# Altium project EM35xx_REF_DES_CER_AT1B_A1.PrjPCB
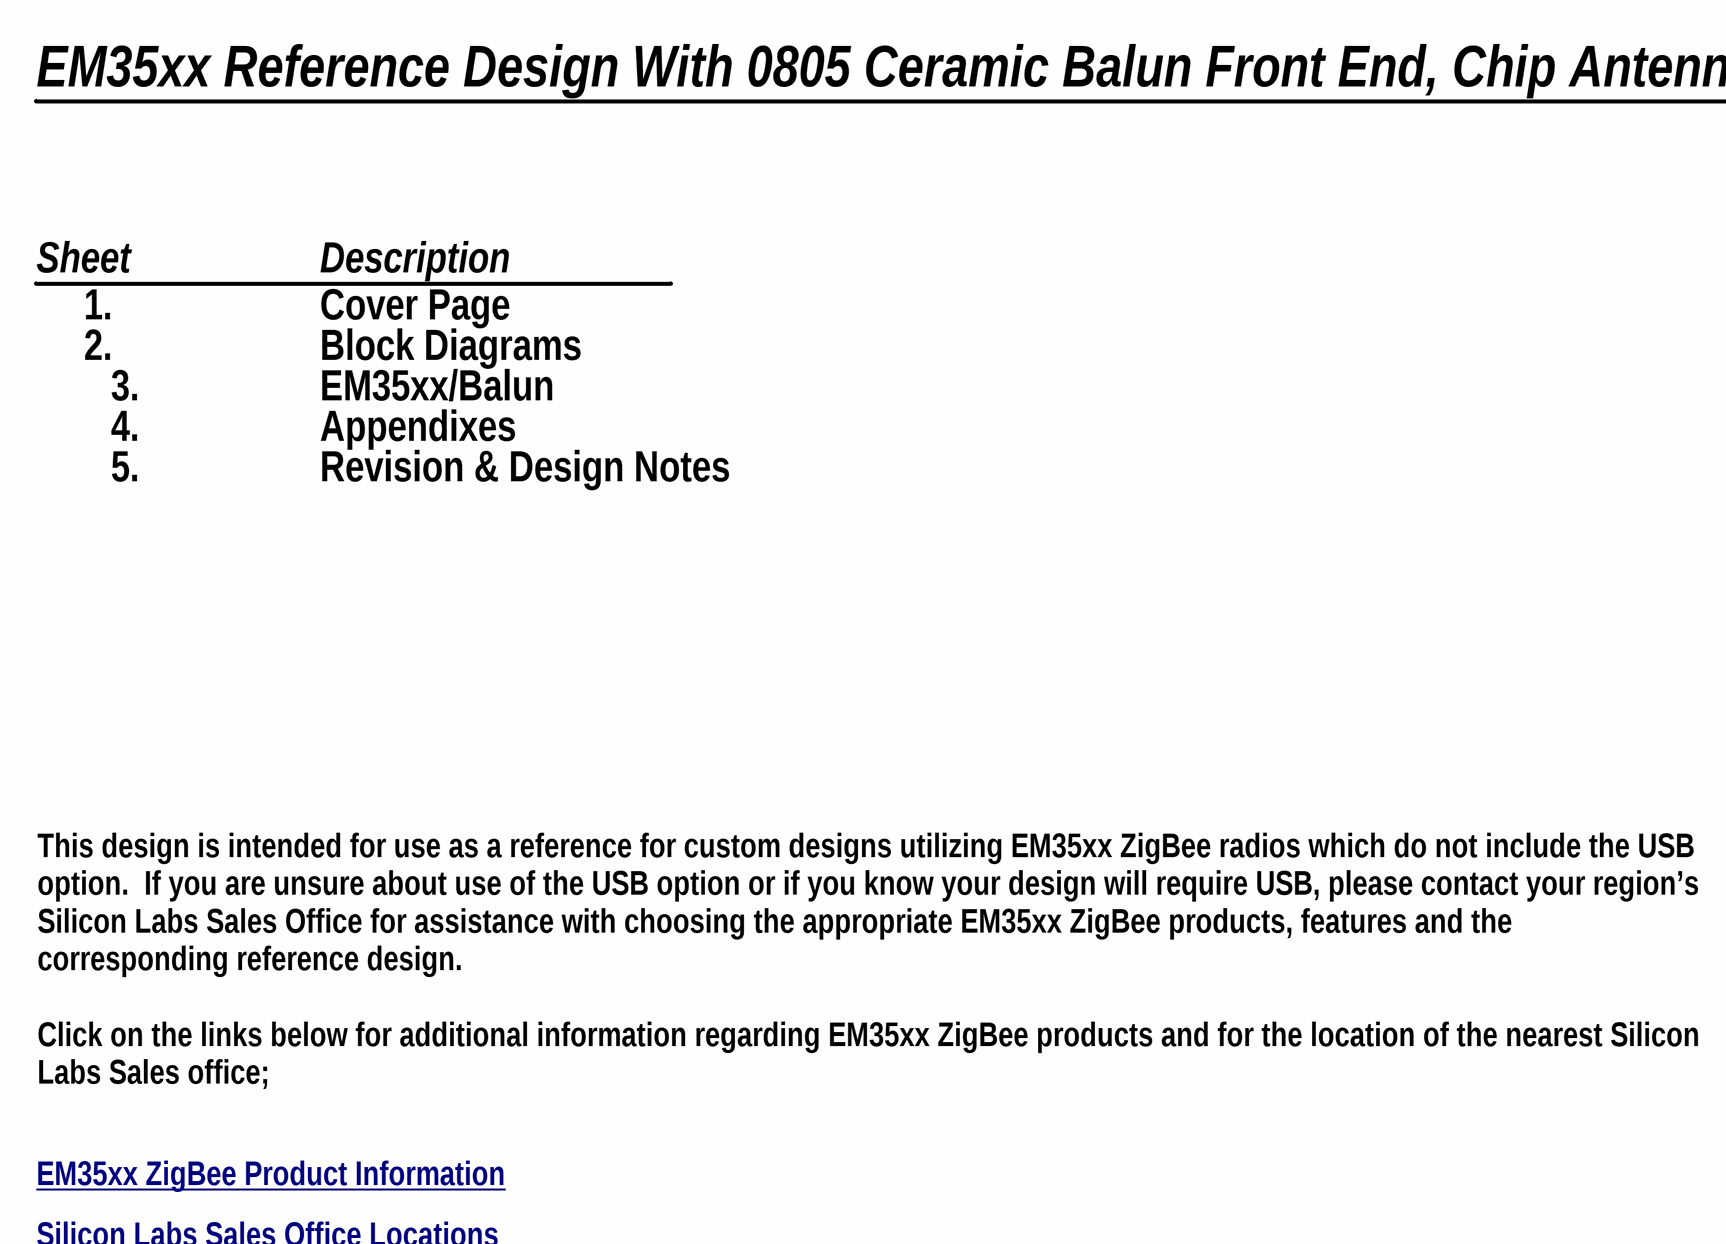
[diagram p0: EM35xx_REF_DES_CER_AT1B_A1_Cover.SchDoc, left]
Board Rev: A1; ClassName: PCB Only; Company Address 1: 25 Thomson Place; Company Address 2: 2nd Floor; Company Address 3: Boston, MA 02210; Company Design Group: MCU & Wireless Division Simplicity Support Group; Company Tel: 617-951-0200; Company Web Site: www.silabs.com; Title: EM35xx Ceramic Balun 2-Layer Reference Design
5 sheets, 52 parts. Net scope: global (net labels, ports and power ports of the same name join across sheets).
Board file: EM35xx_REF_DES_CER_AT1B_A1.PcbDoc
Sheets:
  EM35xx_REF_DES_CER_AT1B_A1_Cover.SchDoc
  EM35xx_REF_DES_CER_AT1B_A1_Block.SchDoc
  EM35xx_REF_DES_CER_AT1B_A1_Main.SchDoc
  EM35xx_REF_DES_CER_AT1B_A1_App.SchDoc
  EM35xx_REF_DES_CER_AT1B_A1_Notes.SchDoc

## Sheet EM35xx_REF_DES_CER_AT1B_A1_Cover.SchDoc: EM35xx/0805 Ceramic Balun Reference Design
size C; Organization: MCU & Wireless Division Simplicity Support Group; Address1: 25 Thomson Place, 2nd Floor; Address2: Boston, MA 02210, USA; Address3: www.silabs.com; Address4: 617-951-0200; Revision: A1; SheetNumber: 1; SheetTotal: 5

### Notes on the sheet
- EM35xx Reference Design With 0805 Ceramic Balun Front End, Chip Antenna, 2 - Layer
- Sheet
- Description
- 1.
- 2.
- Cover Page
- Block Diagrams
- 3.
- EM35xx/Balun
- 4.
- 5.
- Revision & Design Notes
- Appendixes
- This design is intended for use as a reference for custom designs utilizing EM35xx ZigBee radios which do not include the USB option.  If you are unsure about use of the USB option or if you know your design will require USB, please contact your region’s Silicon Labs Sales Office for assistance with choosing the appropriate EM35xx ZigBee products, features and the corresponding reference design.
  Click on the links below for additional information regarding EM35xx ZigBee products and for the location of the nearest Silicon Labs Sales office;
- EM35xx ZigBee Product Information <http://www.silabs.com/products/wireless/zigbee/Pages/default.aspx>
- Silicon Labs Sales Office Locations <http://www.silabs.com/buysample/pages/contact-sales.aspx>

## Sheet EM35xx_REF_DES_CER_AT1B_A1_Block.SchDoc: EM35xx/0805 Ceramic Balun Reference Design
size C; Organization: MCU & Wireless Division Simplicity Support Group; Address1: 25 Thomson Place, 2nd Floor; Address2: Boston, MA 02210, USA; Address3: www.silabs.com; Address4: 617-951-0200; Revision: A1; SheetNumber: 2; SheetTotal: 5
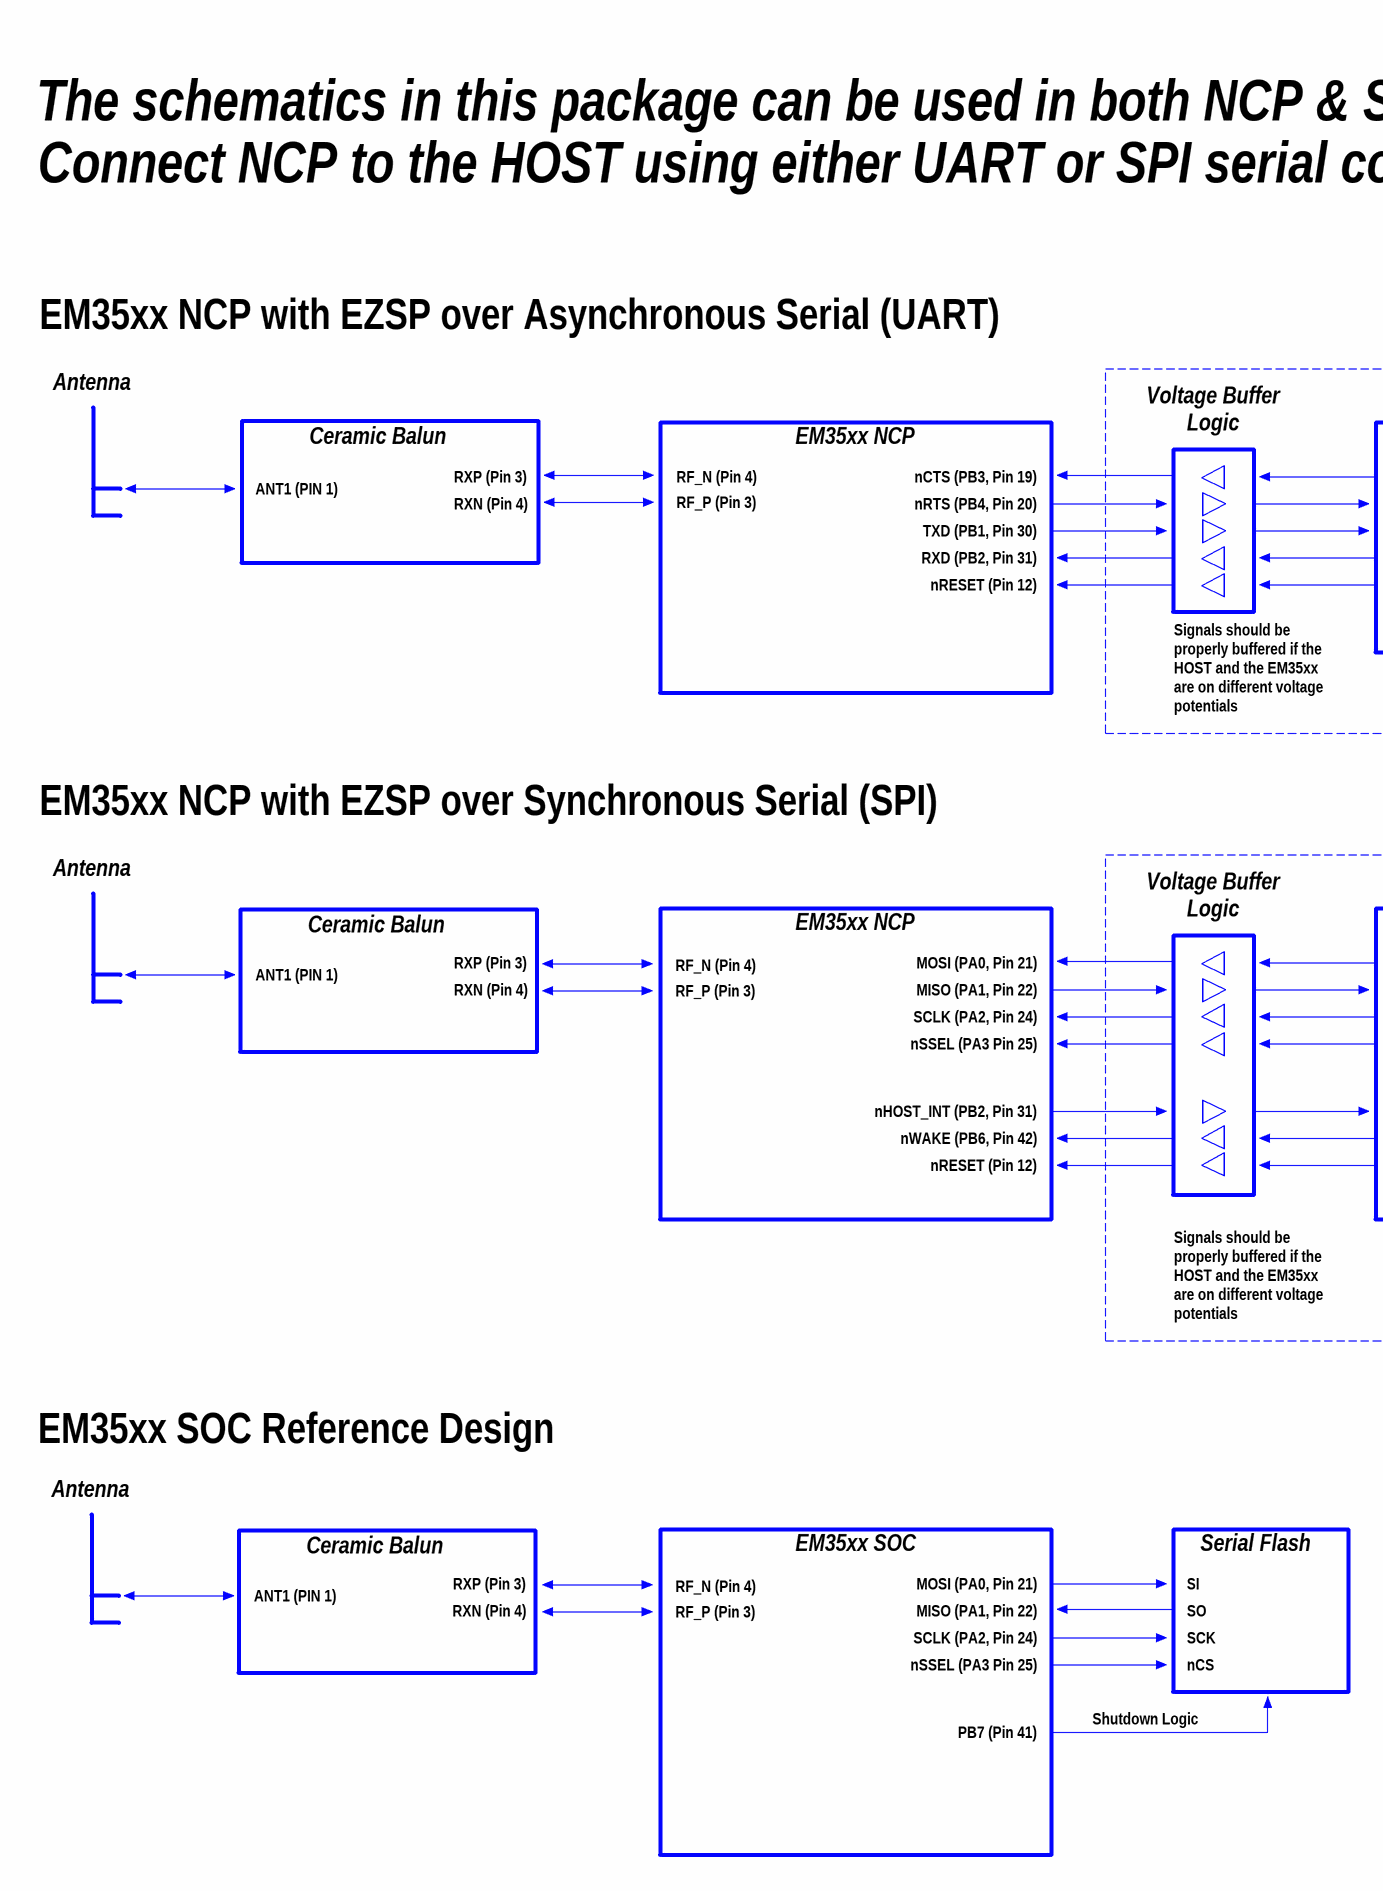
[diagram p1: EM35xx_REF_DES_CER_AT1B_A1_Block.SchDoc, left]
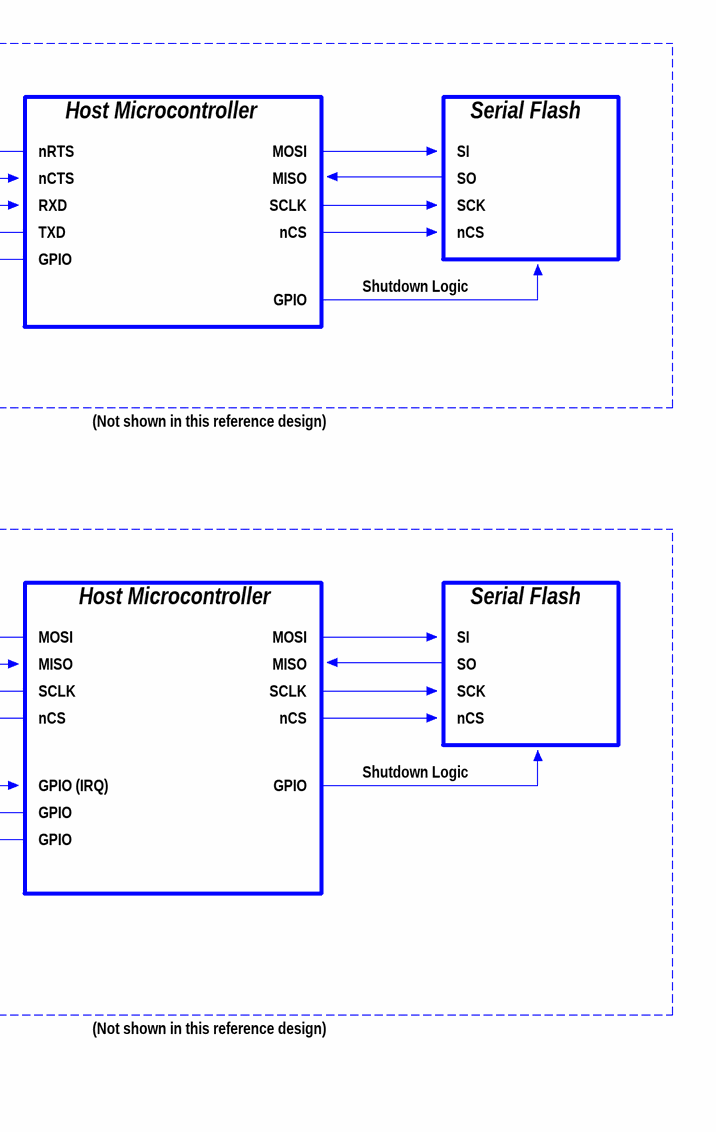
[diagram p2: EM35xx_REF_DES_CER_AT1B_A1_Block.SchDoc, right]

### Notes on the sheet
- The schematics in this package can be used in both NCP & SOC designs involving the EM35xx.
- Connect NCP to the HOST using either UART or SPI serial connection as shown below.
- EM35xx NCP with EZSP over Asynchronous Serial (UART)
- Antenna
- Voltage Buffer
- Ceramic Balun
- EM35xx NCP
- Logic
- Host Microcontroller
- Serial Flash
- ANT1 (PIN 1)
- RXP (Pin 3)
- RXN (Pin 4)
- RF_N (Pin 4)
- RF_P (Pin 3)
- nCTS (PB3, Pin 19)
- nRTS (PB4, Pin 20)
- TXD (PB1, Pin 30)
- nRTS
- nCTS
- RXD
- MOSI
- MISO
- SCLK
- SI
- SO
- SCK
- RXD (PB2, Pin 31)
- nRESET (Pin 12)
- TXD
- GPIO
- nCS
- Shutdown Logic
- Signals should be properly buffered if the HOST and the EM35xx are on different voltage potentials
- EM35xx NCP with EZSP over Synchronous Serial (SPI)
- (Not shown in this reference design)
- MOSI (PA0, Pin 21)
- MISO (PA1, Pin 22)
- SCLK (PA2, Pin 24)
- nSSEL (PA3 Pin 25)
- nHOST_INT (PB2, Pin 31)
- nWAKE (PB6, Pin 42)
- GPIO (IRQ)
- EM35xx SOC Reference Design
- EM35xx SOC
- PB7 (Pin 41)

## Sheet EM35xx_REF_DES_CER_AT1B_A1_Main.SchDoc: EM35xx/0805 Ceramic Balun Reference Design
size C; Organization: MCU & Wireless Division Simplicity Support Group; Address1: 25 Thomson Place, 2nd Floor; Address2: Boston, MA 02210, USA; Address3: www.silabs.com; Address4: 617-951-0200; Revision: A1; SheetNumber: 3; SheetTotal: 5
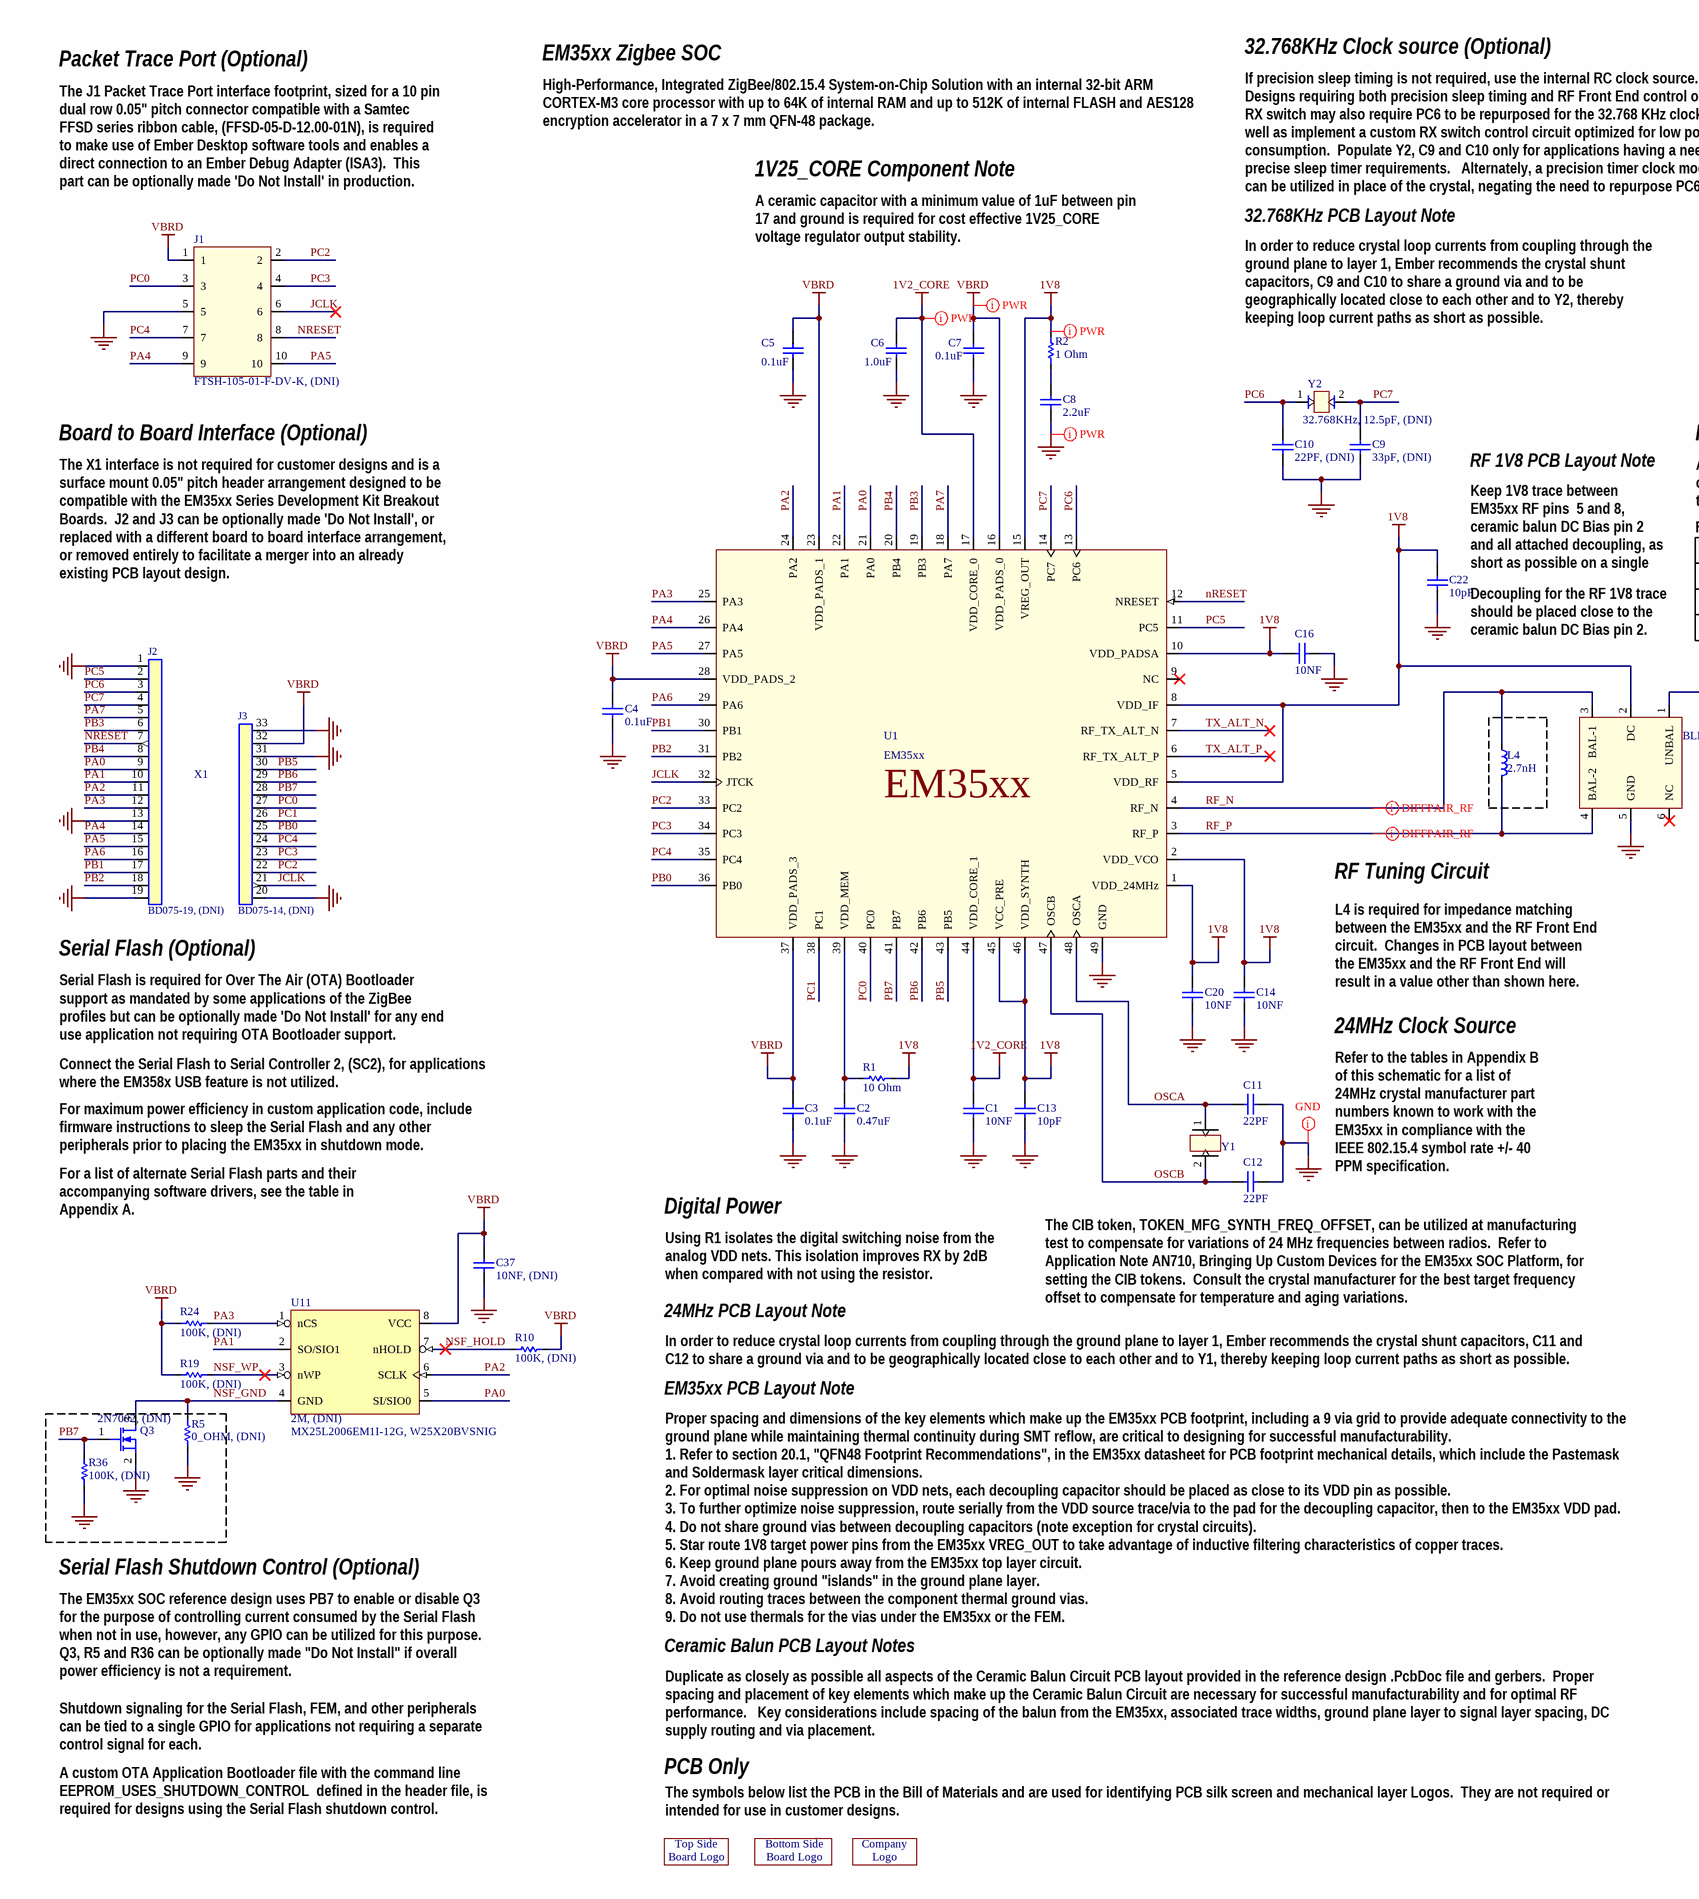
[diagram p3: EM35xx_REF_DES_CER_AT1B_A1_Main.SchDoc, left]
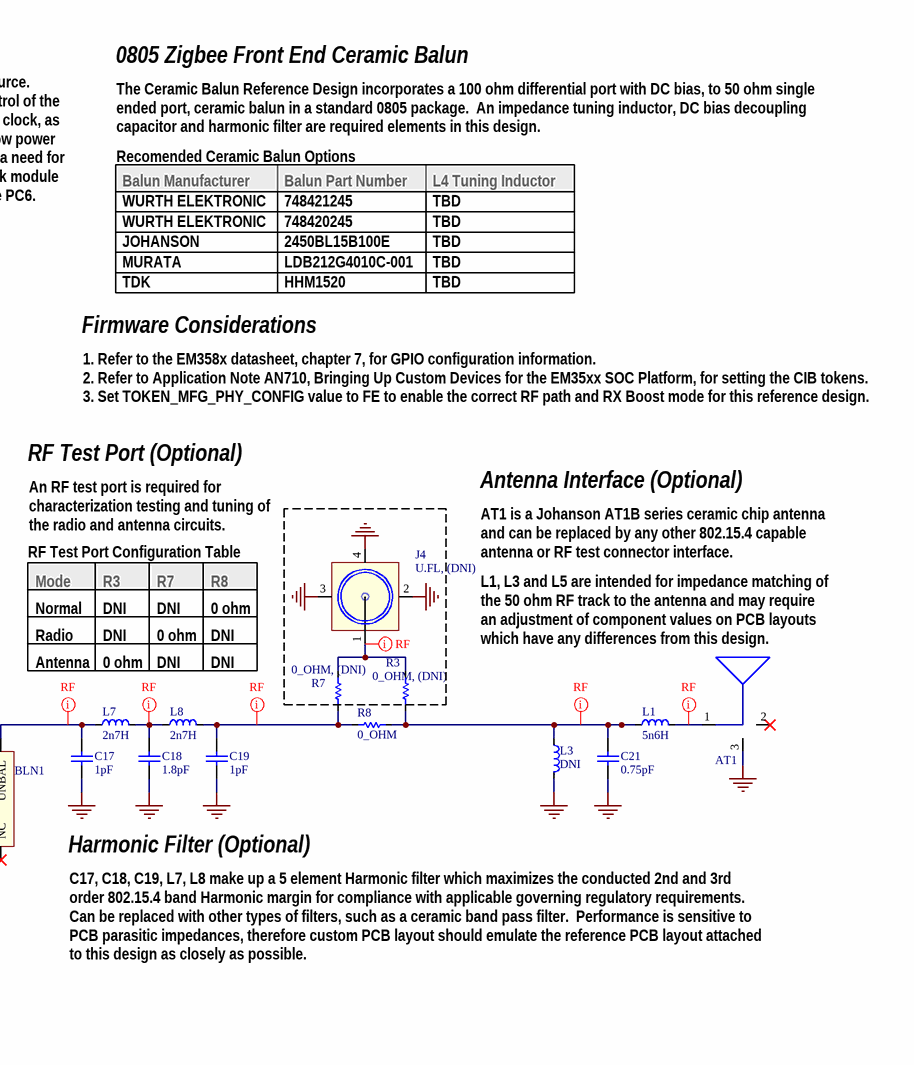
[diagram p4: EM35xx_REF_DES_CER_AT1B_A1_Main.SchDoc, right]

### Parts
AT1  (no value)  [Ant-Johanson-2450AT18B100]
BLN1  CHIP MULTILAYER CERAMIC, 2.4 GHZ. 50/100 Ohm  [BLN_0805]  (value not drawn)
C1  10NF  [C_0402]
C2  0.47uF  [C_0402]
C3  0.1uF  [C_0402]
C4  0.1uF  [C_0402]
C5  0.1uF  [C_0402]
C6  1.0uF  [C_0603]
C7  0.1uF  [C_0402]
C8  2.2uF  [C_0603]
C9  33pF, (DNI)  [C_0402]
C10  22PF, (DNI)  [C_0402]
C11  22PF  [C_0402]
C12  22PF  [C_0402]
C13  10pF  [C_0402]
C14  10NF  [C_0402]
C16  10NF  [C_0402]
C17  1pF  [C_0402]
C18  1.8pF  [C_0402]
C19  1pF  [C_0402]
C20  10NF  [C_0402]
C21  0.75pF  [C_0402]
C22  10pF  [C_0402]
C37  10NF, (DNI)  [C_0402]
J1  FTSH-105-01-F-DV-K, (DNI)  [610-0019-000-REF-DES]
J2  BD075-19, (DNI)  (mechanical)
J3  BD075-14, (DNI)  (mechanical)
J4  U.FL, (DNI)  [UFL-R-SMT_1]
L1  5n6H  [C_0402_Johanson_AT1B]
L3  DNI  [L_0402]
L4  2.7nH  [L_0603]
L7  2n7H  [L_0402]
L8  2n7H  [L_0402]
LOGO1  SiliconLabsLogo_100  [SiliconLabsLogo_100_Mech-16]  (value not drawn)  (no BOM)
PCB1  EM35x Ceramic Balun 2 Layer Reference Design Corporate Logo  [710-0651-009]  (value not drawn)
PCB2  Bottom Silk Screen ID and RoHS Text  [710-0651-009_ROHS]  (value not drawn)  (no BOM)
Q3  2N7002, (DNI)  [SOT23-3L]
R1  10 Ohm  [R_0402]
R2  1 Ohm  [R_0402]
R3  0_OHM, (DNI)  [R_0402]
R5  0_OHM, (DNI)  [R_0402]
R7  0_OHM, (DNI)  [R_0402]
R8  0_OHM  [R_0402]
R10  100K, (DNI)  [R_0402]
R19  100K, (DNI)  [R_0402]
R24  100K, (DNI)  [R_0402]
R36  100K, (DNI)  [R_0402]
U1  EM35xx  [EM357]
U11  2M, (DNI)  PART_NUMBER: MX25L2006EM1I-12G, W25X20BVSNIG  [SOIC127P600-8M]
X1  Dual Row Socket, (DNI)  [EM35X_RCM_MODULE_SIDE_SMT]  (value not drawn)  (no BOM)
Y1  24.000MHZ, 18PF LOAD  [HC-49-SMD]  (value not drawn)
Y2  32.768KHz, 12.5pF, (DNI)  [IL3X]

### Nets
1V2_CORE: C1.1 C6.1 U1.17(VDD_CORE_0) U1.44(VDD_CORE_1)
1V8: BLN1.2(DC) C13.1 C14.1 C16.1 C20.1 C22.1 R1.1 R2.1 U1.1(VDD_24MHz) U1.2(VDD_VCO) U1.5(VDD_RF) U1.8(VDD_IF) U1.10(VDD_PADSA) U1.15(VREG_OUT) U1.45(VCC_PRE) U1.46(VDD_SYNTH)
GND: AT1.3(GND) BLN1.5(GND) C1.2 C2.2 C3.2 C4.2 C5.2 C6.2 C7.2 C8.2 C9.2 C10.2 C11.2 C12.2 C13.2 C14.2 C16.2 C17.2 C18.2 C19.2 C20.2 C21.2 C22.2 C37.2 J1.5 J4.2(GND) J4.3(GND) J4.4(GND) L3.2 Q3.2(S) R5.2 R36.2 U1.49(GND) X1.1(GND) X1.13(GND) X1.19(GND) X1.20(GND) X1.31(GND) X1.33(GND)
VBRD: C3.1 C4.1 C5.1 C7.1 C37.1 J1.1 R10.2 R19.2 R24.2 U1.16(VDD_PADS_0) U1.23(VDD_PADS_1) U1.28(VDD_PADS_2) U1.37(VDD_PADS_3) U11.8(VCC) X1.32(VBRD)
JCLK: J1.6 U1.32(JTCK) X1.21(JCLK)
nRESET: J1.8 U1.12(NRESET) X1.7(nRESET)
NSF_GND: Q3.3(D) R5.1 U11.4(GND)
NSF_HOLD: R10.1 U11.7(nHOLD)
NSF_WP: R19.1 U11.3(nWP)
OSCA: C11.1 U1.48(OSCA) Y1.1(OSCB)
OSCB: C12.1 U1.47(OSCB) Y1.2(OSCA)
PA0: U1.21(PA0) U11.5(SI/SIO0) X1.9(PA0)
PA1: U1.22(PA1) U11.2(SO/SIO1) X1.10(PA1)
PA2: U1.24(PA2) U11.6(SCLK) X1.11(PA2)
PA3: R24.1 U1.25(PA3) U11.1(nCS) X1.12(PA3)
PA4: J1.9 U1.26(PA4) X1.14(PA4)
PA5: J1.10 U1.27(PA5) X1.15(PA5)
PA6: U1.29(PA6) X1.16(PA6)
PA7: U1.18(PA7) X1.5(PA7)
PB0: U1.36(PB0) X1.25(PB0)
PB1: U1.30(PB1) X1.17(PB1)
PB2: U1.31(PB2) X1.18(PB2)
PB3: U1.19(PB3) X1.6(PB3)
PB4: U1.20(PB4) X1.8(PB4)
PB5: U1.43(PB5) X1.30(PB5)
PB6: U1.42(PB6) X1.29(PB6)
PB7: Q3.1(G) R36.1 U1.41(PB7) X1.28(PB7)
PC0: J1.3 U1.40(PC0) X1.27(PC0)
PC1: U1.38(PC1) X1.26(PC1)
PC2: J1.2 U1.33(PC2) X1.22(PC2)
PC3: J1.4 U1.34(PC3) X1.23(PC3)
PC4: J1.7 U1.35(PC4) X1.24(PC4)
PC5: U1.11(PC5) X1.2(PC5)
PC6: C10.1 U1.13(PC6) X1.3(PC6) Y2.1
PC7: C9.1 U1.14(PC7) X1.4(PC7) Y2.2
RF_N: BLN1.3(BAL-1) L4.1 U1.4(RF_N)
RF_P: BLN1.4(BAL-2) L4.2 U1.3(RF_P)
TX_ALT_N: U1.7(RF_TX_ALT_N)
TX_ALT_P: U1.6(RF_TX_ALT_P)
NetAT1_1: AT1.1 L1.2
NetAT1_4: AT1.4 C21.1 L1.1 L3.1 R3.1 R8.2
NetBLN1_1: BLN1.1(UNBAL) C17.1 L7.1
NetC2_1: C2.1 R1.2 U1.39(VDD_MEM)
NetC8_1: C8.1 R2.2
NetC18_1: C18.1 L7.2 L8.1
NetC19_1: C19.1 L8.2 R7.1 R8.1
NetJ4_1: J4.1(SIGNAL) R3.2 R7.2

Not connected (* = marked no-connect by the designer): AT1 2*; BLN1 6(NC)*; U1 9(NC)*

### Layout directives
rule Width Constraint [Pref Width = 20mil    Min Width = 5mil    Max Width = 40mil]: 1V2_CORE, 1V8, VBRD
rule Width Constraint [Pref Width = 28mil    Min Width = 6mil    Max Width = 60mil]; rule Clearance Constraint [Clearance = 6mil]: NetAT1_1, NetAT1_4, NetBLN1_1, NetC18_1, NetC19_1, NetJ4_1
differential pair; rule Width Constraint [Pref Width = 7mil    Min Width = 5mil    Max Width = 10mil]; rule Matched Net Lengths [Tolerance = 2.5mil]: RF_N, RF_P
rule Clearance Constraint [Clearance = 9.5mil]: GND
rule Width Constraint [Pref Width = 20mil    Min Width = 5mil    Max Width = 40mil]; rule Short-Circuit Constraint [Short Circuit - Allowed]: GND

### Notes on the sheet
- Packet Trace Port (Optional)
- EM35xx Zigbee SOC
- 32.768KHz Clock source (Optional)
- 0805 Zigbee Front End Ceramic Balun
- High-Performance, Integrated ZigBee/802.15.4 System-on-Chip Solution with an internal 32-bit ARM CORTEX-M3 core processor with up to 64K of internal RAM and up to 512K of internal FLASH and AES128 encryption accelerator in a 7 x 7 mm QFN-48 package.
- The Ceramic Balun Reference Design incorporates a 100 ohm differential port with DC bias, to 50 ohm single ended port, ceramic balun in a standard 0805 package.  An impedance tuning inductor, DC bias decoupling capacitor and harmonic filter are required elements in this design.
- Recomended Ceramic Balun Options
- The J1 Packet Trace Port interface footprint, sized for a 10 pin dual row 0.05" pitch connector compatible with a Samtec FFSD series ribbon cable, (FFSD-05-D-12.00-01N), is required to make use of Ember Desktop software tools and enables a direct connection to an Ember Debug Adapter (ISA3).  This part can be optionally made 'Do Not Install' in production.
- 1V25_CORE Component Note
- If precision sleep timing is not required, use the internal RC clock source.  Designs requiring both precision sleep timing and RF Front End control of the RX switch may also require PC6 to be repurposed for the 32.768 KHz clock, as well as implement a custom RX switch control circuit optimized for low power consumption.  Populate Y2, C9 and C10 only for applications having a need for precise sleep timer requirements.   Alternately, a precision timer clock module can be utilized in place of the crystal, negating the need to repurpose PC6.
- WURTH ELEKTRONIC
- Balun Manufacturer
- 748421245
- Balun Part Number
- L4 Tuning Inductor
- TBD
- A ceramic capacitor with a minimum value of 1uF between pin 17 and ground is required for cost effective 1V25_CORE voltage regulator output stability.
- 32.768KHz PCB Layout Note
- JOHANSON
- MURATA
- TDK
- 2450BL15B100E
- 748420245
- LDB212G4010C-001
- HHM1520
- In order to reduce crystal loop currents from coupling through the ground plane to layer 1, Ember recommends the crystal shunt capacitors, C9 and C10 to share a ground via and to be geographically located close to each other and to Y2, thereby keeping loop current paths as short as possible.
- Firmware Considerations
- 1. Refer to the EM358x datasheet, chapter 7, for GPIO configuration information.
  2. Refer to Application Note AN710, Bringing Up Custom Devices for the EM35xx SOC Platform, for setting the CIB tokens.
  3. Set TOKEN_MFG_PHY_CONFIG value to FE to enable the correct RF path and RX Boost mode for this reference design.
- Board to Board Interface (Optional)
- RF 1V8 PCB Layout Note
- RF Test Port (Optional)
- Antenna Interface (Optional)
- An RF test port is required for characterization testing and tuning of the radio and antenna circuits.
- (near J4) RF Test Port Configuration Table
- AT1 is a Johanson AT1B series ceramic chip antenna and can be replaced by any other 802.15.4 capable antenna or RF test connector interface.
- The X1 interface is not required for customer designs and is a surface mount 0.05" pitch header arrangement designed to be compatible with the EM35xx Series Development Kit Breakout Boards.  J2 and J3 can be optionally made 'Do Not Install', or replaced with a different board to board interface arrangement, or removed entirely to facilitate a merger into an already existing PCB layout design.
- (near C22) Keep 1V8 trace between EM35xx RF pins  5 and 8, ceramic balun DC Bias pin 2 and all attached decoupling, as short as possible on a single layer.
- Mode
- Normal
- R3
- DNI
- R7
- R8
- 0 ohm
- (near C22) Decoupling for the RF 1V8 trace should be placed close to the ceramic balun DC Bias pin 2.
- Antenna
- Radio
- L1, L3 and L5 are intended for impedance matching of the 50 ohm RF track to the antenna and may require an adjustment of component values on PCB layouts which have any differences from this design.
- Harmonic Filter (Optional)
- RF Tuning Circuit
- C17, C18, C19, L7, L8 make up a 5 element Harmonic filter which maximizes the conducted 2nd and 3rd order 802.15.4 band Harmonic margin for compliance with applicable governing regulatory requirements.   Can be replaced with other types of filters, such as a ceramic band pass filter.  Performance is sensitive to PCB parasitic impedances, therefore custom PCB layout should emulate the reference PCB layout attached to this design as closely as possible.
- (near X1) Serial Flash (Optional)
- L4 is required for impedance matching between the EM35xx and the RF Front End circuit.  Changes in PCB layout between the EM35xx and the RF Front End will result in a value other than shown here.
- (near J2) Serial Flash is required for Over The Air (OTA) Bootloader support as mandated by some applications of the ZigBee profiles but can be optionally made 'Do Not Install' for any end use application not requiring OTA Bootloader support.
- 24MHz Clock Source
- (near J2) Connect the Serial Flash to Serial Controller 2, (SC2), for applications where the EM358x USB feature is not utilized.
- For maximum power efficiency in custom application code, include firmware instructions to sleep the Serial Flash and any other peripherals prior to placing the EM35xx in shutdown mode.
- Refer to the tables in Appendix B of this schematic for a list of 24MHz crystal manufacturer part numbers known to work with the EM35xx in compliance with the IEEE 802.15.4 symbol rate +/- 40 PPM specification.
- For a list of alternate Serial Flash parts and their accompanying software drivers, see the table in Appendix A.
- Digital Power
- Using R1 isolates the digital switching noise from the analog VDD nets. This isolation improves RX by 2dB when compared with not using the resistor.
- (near C12) The CIB token, TOKEN_MFG_SYNTH_FREQ_OFFSET, can be utilized at manufacturing test to compensate for variations of 24 MHz frequencies between radios.  Refer to Application Note AN710, Bringing Up Custom Devices for the EM35xx SOC Platform, for setting the CIB tokens.  Consult the crystal manufacturer for the best target frequency offset to compensate for temperature and aging variations.
- In order to reduce crystal loop currents from coupling through the ground plane to layer 1, Ember recommends the crystal shunt capacitors, C11 and C12 to share a ground via and to be geographically located close to each other and to Y1, thereby keeping loop current paths as short as possible.
- 24MHz PCB Layout Note
- EM35xx PCB Layout Note
- Serial Flash Shutdown Control (Optional)
- Proper spacing and dimensions of the key elements which make up the EM35xx PCB footprint, including a 9 via grid to provide adequate connectivity to the ground plane while maintaining thermal continuity during SMT reflow, are critical to designing for successful manufacturability.
  1. Refer to section 20.1, "QFN48 Footprint Recommendations", in the EM35xx datasheet for PCB footprint mechanical details, which include the Pastemask and Soldermask layer critical dimensions.
  2. For optimal noise suppression on VDD nets, each decoupling capacitor should be placed as close to its VDD pin as possible.
  3. To further optimize noise suppression, route serially from the VDD source trace/via to the pad for the decoupling capacitor, then to the EM35xx VDD pad.
  4. Do not share ground vias between decoupling capacitors (note exception for crystal circuits).
  5. Star route 1V8 target power pins from the EM35xx VREG_OUT to take advantage of inductive filtering characteristics of copper traces.
  6. Keep ground plane pours away from the EM35xx top layer circuit.
  7. Avoid creating ground "islands" in the ground plane layer.
  8. Avoid routing traces between the component thermal ground vias.
  9. Do not use thermals for the vias under the EM35xx or the FEM.
- The EM35xx SOC reference design uses PB7 to enable or disable Q3 for the purpose of controlling current consumed by the Serial Flash when not in use, however, any GPIO can be utilized for this purpose.  Q3, R5 and R36 can be optionally made "Do Not Install" if overall power efficiency is not a requirement.
- Ceramic Balun PCB Layout Notes
- Shutdown signaling for the Serial Flash, FEM, and other peripherals can be tied to a single GPIO for applications not requiring a separate control signal for each.
- Duplicate as closely as possible all aspects of the Ceramic Balun Circuit PCB layout provided in the reference design .PcbDoc file and gerbers.  Proper spacing and placement of key elements which make up the Ceramic Balun Circuit are necessary for successful manufacturability and for optimal RF performance.   Key considerations include spacing of the balun from the EM35xx, associated trace widths, ground plane layer to signal layer spacing, DC supply routing and via placement.
- PCB Only
- The symbols below list the PCB in the Bill of Materials and are used for identifying PCB silk screen and mechanical layer Logos.  They are not required or intended for use in customer designs.
- A custom OTA Application Bootloader file with the command line  EEPROM_USES_SHUTDOWN_CONTROL  defined in the header file, is required for designs using the Serial Flash shutdown control.

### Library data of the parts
AT1 = 600-0044-000: Part Description: ANTENNA, CERAMIC CHIP DIELECTRIC, 3.2X1.6X0.5MM, 2.45GHZ
BLN1 = 566-0075-000: Balun 0805; Part Description: BALUN, CHIP MULTILAYER CERAMIC, 2.4 GHZ. 50/100 OHM, -40C TO 85C, 0805 (2012 METRIC); Temperature Coefficient: -40C to 85C
C1 C14 C20 = 550-0036-000: Part Description: CAPACITOR, CERAMIC, 10NF, +/-10%, 6.3V, -55C TO 125C, X7R, 0402 (1005 METRIC); MANUFACTURER: MURATA; PART_NUMBER: GRM155R70J103KA01D; VOLTAGE: 6.3V; TOLERANCE: +/-10%; Temperature Coefficient: -55C to 125C, X7R
C2 = 550-0037-000: Part Description: CAPACITOR, CERAMIC, 0.47UF, +/- 10%, 6.3V, -55C TO 85C, X5R, 0402 (1005 METRIC); MANUFACTURER: MURATA; PART_NUMBER: GRM155R60J474KE19D; VOLTAGE: 6.3V; TOLERANCE: +/- 10%; Temperature Coefficient: -55C to 85C, X5R
C3-C5 C7 = 550-0034-000: Part Description: CAPACITOR, CERAMIC, 0.1UF, +/-10%, 6.3V, -55C TO 125C, X7R, 0402 (1005 METRIC); MANUFACTURER: MURATA; PART_NUMBER: GRM155R70J104KA01D; VOLTAGE: 6.3V; TOLERANCE: +/-10%; Temperature Coefficient: -55C to 125C, X7R
C6 = 550-0033-000: Part Description: CAPACITOR, CERAMIC, 1.0UF, +/-10%, 10V, -55C TO 125C, X7R, 0603 (1608 METRIC); MANUFACTURER: TAIYO YUDEN LTD; PART_NUMBER: LMK107B7105KA-T; VOLTAGE: 10V; TOLERANCE: +/-10%; Temperature Coefficient: -55C to 125C, X7R
C8 = 550-0038-000: Part Description: CAPACITOR, CERAMIC, 2.2UF, +/-10%, 6.3V, -55C TO 125C, X7R, 0603 (1608 METRIC); MANUFACTURER: MURATA; PART_NUMBER: CL10B225KQ8NNNC; VOLTAGE: 6.3V; TOLERANCE: +/-10%; Temperature Coefficient: -55C to 125C, X7R
C9 = 550-0039-000-DNI: Part Description: CAPACITOR, CERAMIC, 33PF, (DNI), +/-5%, 50V, -55C TO 125C, C0G, NP0, 0402 (1005 METRIC); MANUFACTURER: SAMSUNG ELECTRONICS; PART_NUMBER: CL05C330JB5NNNC; VOLTAGE: 50V; TOLERANCE: +/-5%; Temperature Coefficient: -55C to 125C, C0G, NP0
C10 = 550-2201-050-DNI: Part Description: CAPACITOR, CERAMIC, 22PF, +/-5%, 50V, -55C TO 125C, 0402 (1005 METRIC); MANUFACTURER: MURATA; PART_NUMBER: GRM1555C1H220JZ01D; VOLTAGE: 50V; TOLERANCE: +/-5%; Temperature Coefficient: -55C to 125C
C11 C12 = 550-2201-050: Part Description: CAPACITOR, CERAMIC, 22PF, +/-5%, 50V, -55C TO 125C, 0402 (1005 METRIC); MANUFACTURER: MURATA; PART_NUMBER: GRM1555C1H220JZ01D; VOLTAGE: 50V; TOLERANCE: +/-5%; Temperature Coefficient: -55C to 125C
C13 C22 = 550-1001-050: Part Description: CAPACITOR, CERAMIC, 10PF, +/-5%, 50V, -55C TO 125C, 0402 (1005 METRIC); MANUFACTURER: MURATA; PART_NUMBER: GRM1555C1H100JZ01D; VOLTAGE: 50V; TOLERANCE: +/-5%; Temperature Coefficient: -55C to 125C
C16 = 550-0036-000: Part Description: CAPACITOR, CERAMIC, 10NF, +/-10%, 6.3V, -55C TO 125C, X7R, 0402 (1005 METRIC); MANUFACTURER: MURATA; PART_NUMBER: GRM155R70J103KA01D; TOLERANCE: +/-10%; Temperature Coefficient: -55C to 125C, X7R; VOLTAGE: 6.3V
C17 C19 = 550-0040-000: Part Description: CAPACITOR, CERAMIC, 1PF, +/-0.25PF, 50V, -55C TO 125C, C0G, NP0, 0402 (1005 METRIC); MANUFACTURER: SAMSUNG ELECTRONICS; PART_NUMBER: CL05C010CB5NNNC; VOLTAGE: 50V; TOLERANCE: +/-0.25pF; Temperature Coefficient: -55C to 125C, C0G, NP0
C18 = 550-1P8A-050: Part Description: CAPACITOR, CERAMIC, 1.8PF, +/-0.25PF, 50V, -55C TO 125C, C0G, NP0, 0402 (1005 METRIC); MANUFACTURER: MURATA; PART_NUMBER: GRM1555C1H1R8CZ01D; VOLTAGE: 50V; TOLERANCE: +/-0.25pF; Temperature Coefficient: -55C to 125C, C0G, NP0
C21 = 550-0045-000: Part Description: CAPACITOR, CERAMIC, 0.75PF, +/-0.25PF, 50V, -55C TO 125C, C0G, NP0, 0402 (1005 METRIC); MANUFACTURER: MURATA; PART_NUMBER: GRM1555C1HR75CA01D; VOLTAGE: 50V; TOLERANCE: +/-0.25pF; Temperature Coefficient: -55C to 125C, C0G, NP0
C37 = 550-0036-000-DNI: Part Description: CAPACITOR, CERAMIC, 10NF, (DNI), +/-10%, 6.3V, -55C TO 125C, X7R, 0402 (1005 METRIC); MANUFACTURER: MURATA; PART_NUMBER: GRM155R70J103KA01D; VOLTAGE: 6.3V; TOLERANCE: +/-10%; Temperature Coefficient: -55C to 125C, X7R
J1 = 610-0045-000-DNI: CONNECTOR, HEADER, SHROUDED, 10 POSITION, DUAL ROW, VERTICAL, 0.050"; Part Description: CONNECTOR, HEADER, FTSH-105-01-F-DV-K, (DNI), 10 POSITION, DUAL ROW, VERTICAL, 0.050"
J2 = 610-0086-000-DNI: 19 pin, 0.050" pitch  RCM socket, SMT; Part Description: CONNECTOR, RECEPTACLE, BD075-19, (DNI), SURFACE MOUNT VERTICAL; MANUFACTURER: Global Connector Technology; PART_NUMBER: BD075-19-A-1-L-C
J3 = 610-0087-000-DNI: 14 pin, 0.050" pitch  RCM socket, SMT; Part Description: CONNECTOR, RECEPTACLE, BD075-14, (DNI), SURFACE MOUNT VERTICAL; MANUFACTURER: Global Connector Technology; PART_NUMBER: BD075-14-A-1-L-C
J4 = 610-0081-000-DNI: U.FL RF Coaxial Connector; Part Description: CONNECTOR, RECEPTACLE, U.FL, (DNI), RF COAXIAL, SMT; MANUFACTURER: Molex; PART_NUMBER: 73412-0110
L1 = 566-0077-000: Design Placeholder; Part Description: INDUCTOR, MULTI-LAYER FILM, 5N6H, +/-0.3NH, 300MA, -55C TO 125C, 0402 (1005 METRIC); MANUFACTURER: MURATA; PART_NUMBER: LQG15HS5N6S02D; Current Rating: 300MA; TOLERANCE: +/-0.3NH; Temperature Coefficient: -55C to 125C
L3 = 566-0000-TBD: Design Placeholder; Part Description: INDUCTOR, TBD
L4 = 566-0076-000: Design Placeholder; Part Description: INDUCTOR, MULTI-LAYER FILM, 2.7NH, +/-0.3NH, -40C TO 85C, 0603 (1608 METRIC); MANUFACTURER: MURATA; PART_NUMBER: LQG18HN2N7S00D; TOLERANCE: +/-0.3NH; Temperature Coefficient: -40C to 85C
L7 L8 = 566-2N7A-000: Design Placeholder; Part Description: INDUCTOR, MULTI-LAYER FILM, 2N7H, +/-0.3NH, 300MA, -55C TO 125C, 0402 (1005 METRIC); MANUFACTURER: MURATA; PART_NUMBER: LQG15HS2N7S02D; Current Rating: 300MA; TOLERANCE: +/-0.3NH; Temperature Coefficient: -55C to 125C
LOGO1 = SiliconLabsLogo_100: Company Logo in PCB Title Block
PCB1 = 710-0651-009: PCB BoM ID and Top Side Silk Screen Identifier; Part Description: MECHANICAL, PCB, EM35X CERAMIC BALUN 2 LAYER REFERENCE DESIGN CORPORATE LOGO
PCB2 = 710-0651-009_ROHS: Bottom Side Silk Screen Identifier; Part Description: MECHANICAL, PCB, EM35X CERAMIC BALUN 2 LAYER REFERENCE DESIGN BOTTOM SIDE CORPORATE LOGO W/ROHS LOGO; VALUE: EM35x Ceramic Balun 2 Layer Reference Design Bottom Side Corporate Logo w/ROHS logo
Q3 = 545-0047-000-DNI: MOSFET N-Channel; Part Description: MOSFET, 2N7002, (DNI), 300MA, 830MW, 60V, TO-236-3, SC-59, SOT-23-3; VOLTAGE: 60V; POWER: 830mW; Current Rating: 300mA
R1 = 555-1001-010: Part Description: RESISTOR, THICK FILM, 10 OHM, +/-1%, 0.1W, 1/10W, 0402 (1005 METRIC); POWER: 0.1W, 1/10W; TOLERANCE: +/-1%; Temperature Coefficient: +/-100ppm/C
R2 = 555-1R05-016: Part Description: RESISTOR, THICK FILM, 1 OHM, +/-5%, 0.1W, 1/10W, 0402 (1005 METRIC); POWER: 0.1W, 1/10W; TOLERANCE: +/-5%; Temperature Coefficient: -100/ +600ppm/C
R3 R5 R7 = 555-0000-000-DNI: Part Description: RESISTOR, THICK FILM, 0_OHM, (DNI), JUMPER, 1/10W, 0402 (1005 METRIC); MANUFACTURER: SAMSUNG ELECTRONICS; PART_NUMBER: RC1005J000CS; POWER: 1/10W; TOLERANCE: Jumper; Temperature Coefficient: -100/ +600ppm/C
R8 = 555-0000-000: Part Description: RESISTOR, THICK FILM, 0_OHM, JUMPER, 1/10W, 0402 (1005 METRIC); POWER: 1/10W; TOLERANCE: Jumper; Temperature Coefficient: -100/ +600ppm/C
R10 R19 R36 = 555-1045-016-DNI: Part Description: RESISTOR, THICK FILM, 100K, (DNI), +/-5%, 0.1W, 1/10W, 0402 (1005 METRIC); POWER: 0.1W, 1/10W; TOLERANCE: +/-5%; Temperature Coefficient: +/-200ppm/C
R24 = 555-1045-016-DNI: Part Description: RESISTOR, THICK FILM, 100K, (DNI), +/-5%, 0.1W, 1/10W, 0402 (1005 METRIC); TOLERANCE: +/-5%; POWER: 0.1W, 1/10W; Temperature Coefficient: +/-200ppm/C
U1 = 540-035XX-000: IC, EM357, ZIGBEE/802.15.4 RF SOLUTION, ARM CORTEX-M3, 12K RAM, 192K FLASH, QFN-48; Part Description: IC, COMMUNICATIONS, EM35XX, -40C TO 85C, SOC, ZIGBEE/802.15.4 RF TRANSCEIVER, ARM CORTEX-M3, TO 12 - 64K RAM, 128 - 512K FLASH, 48-QFN; MANUFACTURER: SILICON LABS; PART_NUMBER: 540-035x-000
U11 = 510-1040-000-DNI: IC - MEMORY, SERIAL FLASH, 2M (2M X 1, 1M X 2), 2.7 V - 3.6 V, -40C  85C, 8-SOIC (0.154", 3.90MM WIDTH); Part Description: IC - PROGRAMMABLE MEMORY - BLANK, SERIAL FLASH, 2M, (DNI), 2.7 V - 3.6 V, -40C  85C, 8-SOIC (0.154IN, 3.90MM WIDTH); MANUFACTURER: MACRONIX, WINBOND
X1 = 610-0010-DNI: Part Description: CONNECTOR, INTERFACE, RCM, DEV KIT, EM35X, DUAL ROW SOCKET, (DNI)
Y1 = 565-2400-009: OSCILLATOR, CRYSTAL, 24.000MHZ, 18PF LOAD, +/-10PPM TOLERANCE, +/-25PPM STABILITY, -40C TO 85C, AT49; MANUFACTURER: ABRACON
Y2 = 565-3271-001-DNI: Part Description: OSCILLATOR, CRYSTAL, 32.768KHZ, 12.5PF, (DNI), +/-20PPM, -40C TO 85C, 2-SMD; MANUFACTURER: ABRACON; PART_NUMBER: ABS07-32.768KHZ-T; TOLERANCE: +/-20ppm; Temperature Coefficient: -40C to 85C

## Sheet EM35xx_REF_DES_CER_AT1B_A1_App.SchDoc: EM35xx/0805 Ceramic Balun Reference Design
size C; Organization: MCU & Wireless Division Simplicity Support Group; Address1: 25 Thomson Place, 2nd Floor; Address2: Boston, MA 02210, USA; Address3: www.silabs.com; Address4: 617-951-0200; Revision: A1; SheetNumber: 4; SheetTotal: 5
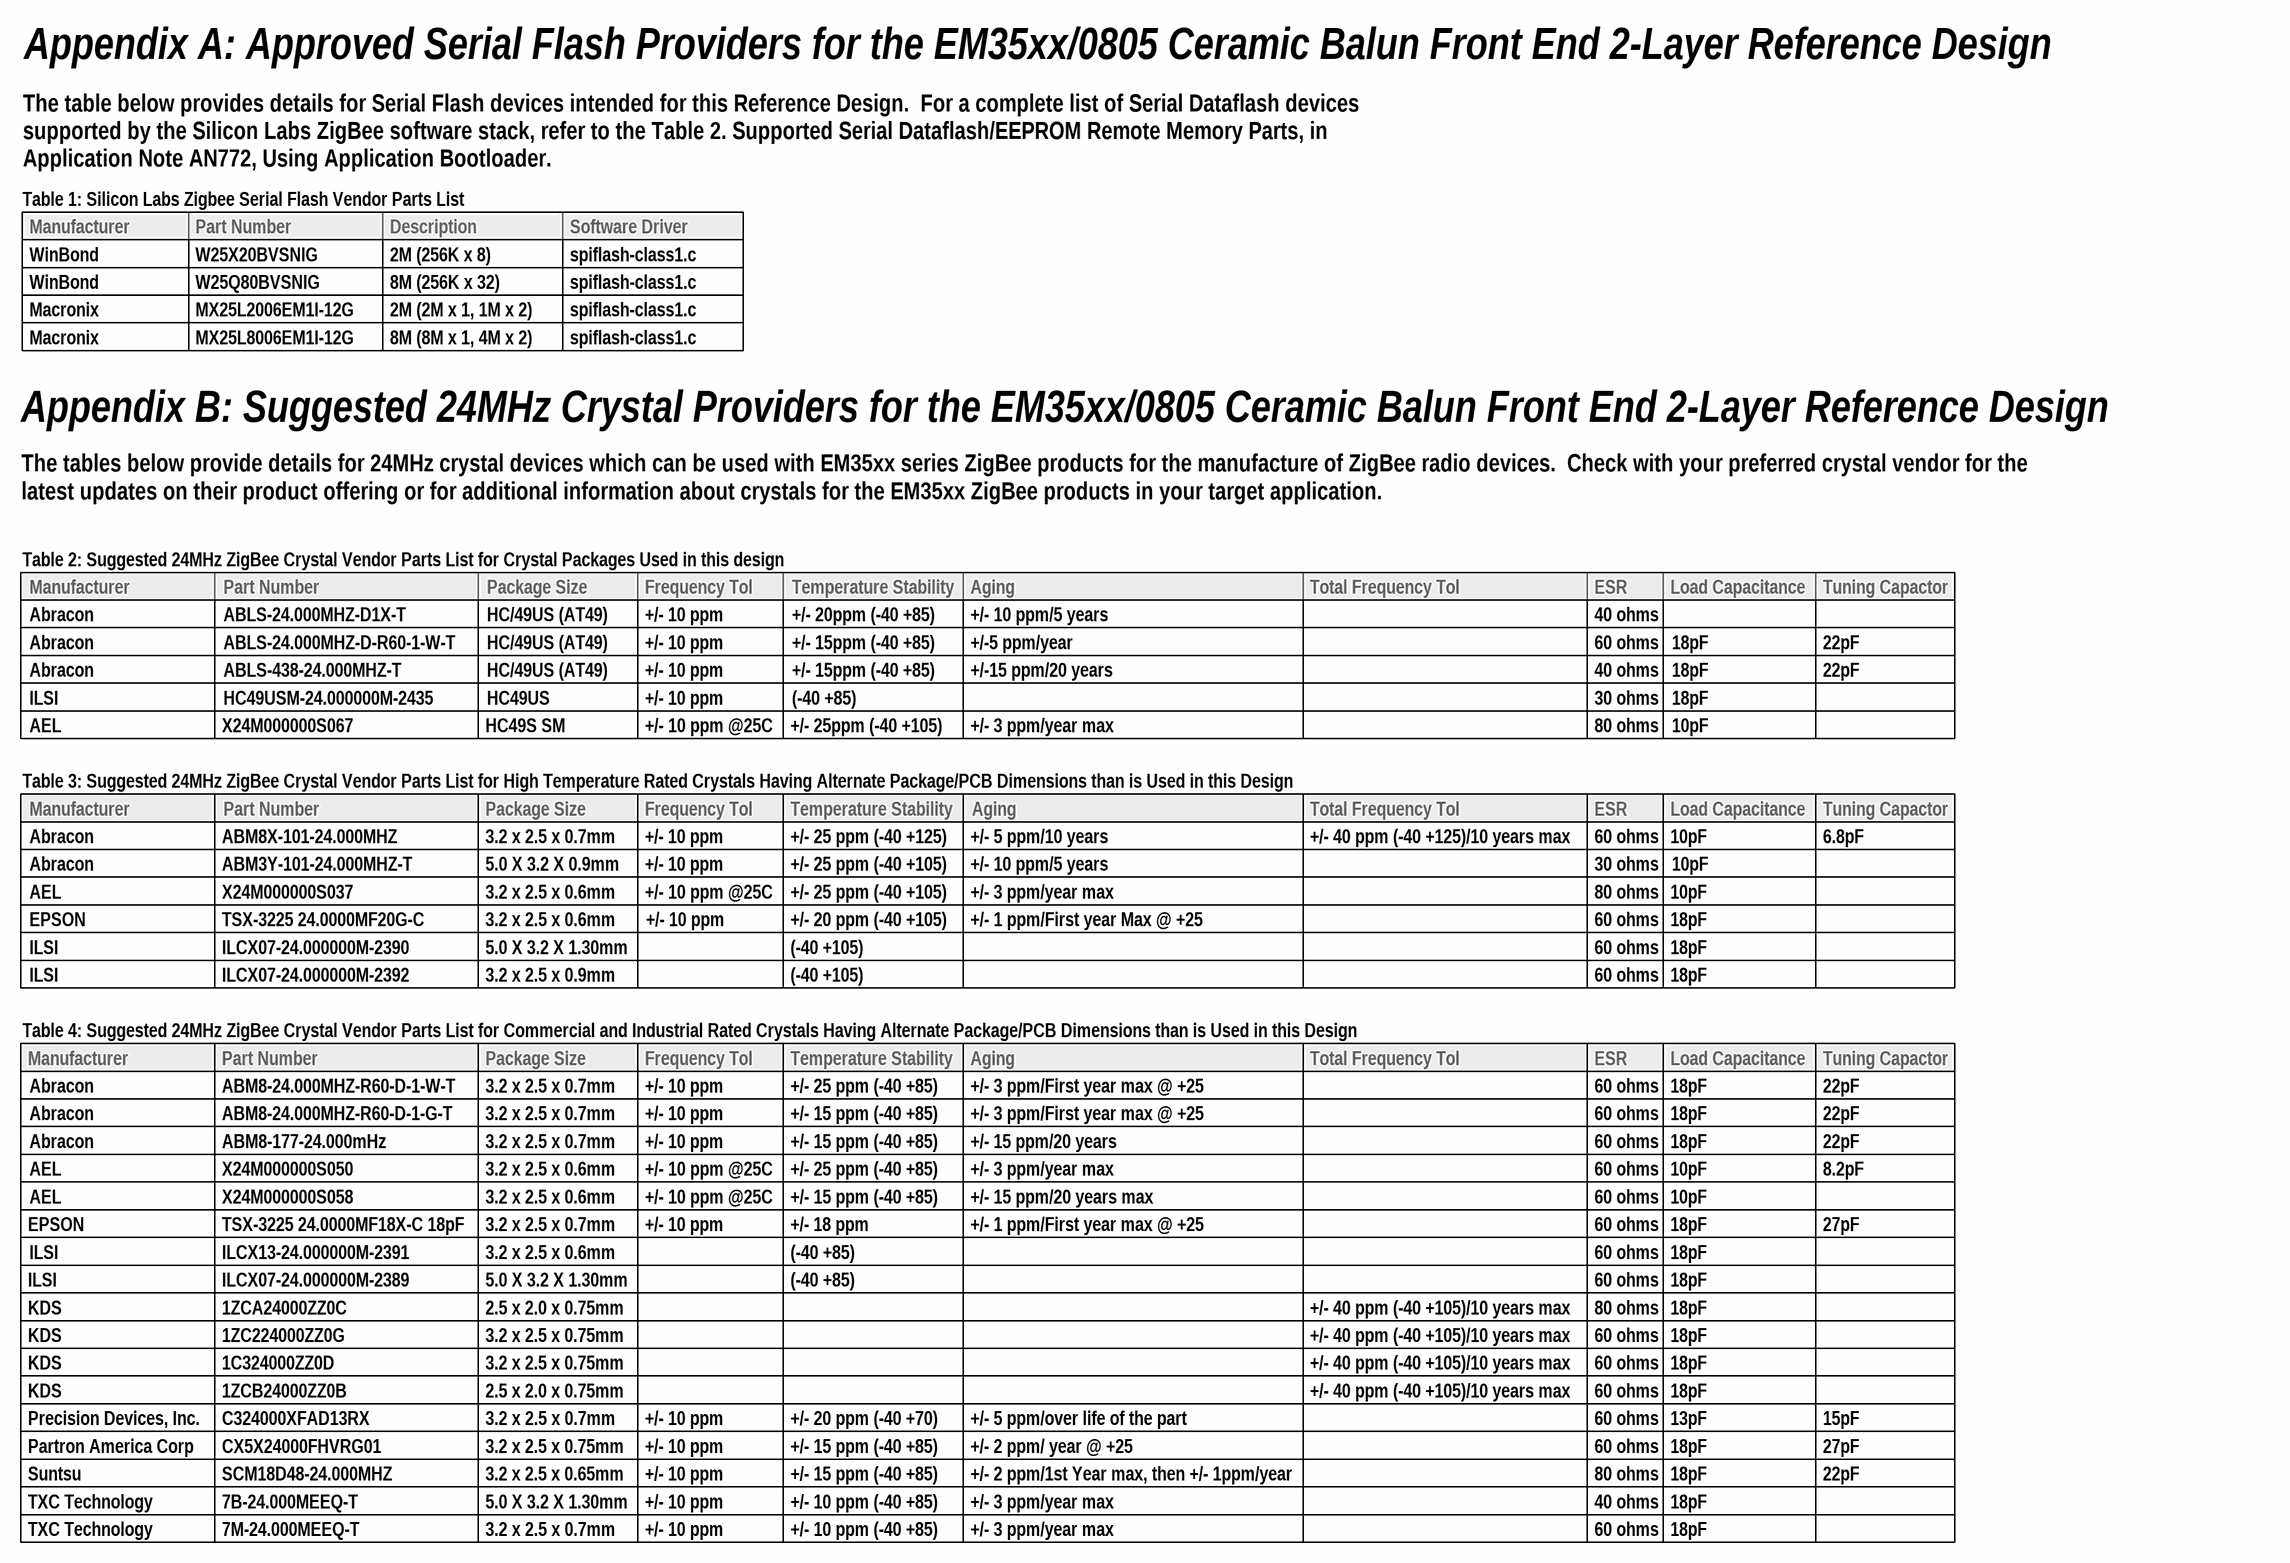
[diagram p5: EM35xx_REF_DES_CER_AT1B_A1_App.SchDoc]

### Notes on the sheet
- Appendix A: Approved Serial Flash Providers for the EM35xx/0805 Ceramic Balun Front End 2-Layer Reference Design
- The table below provides details for Serial Flash devices intended for this Reference Design.  For a complete list of Serial Dataflash devices supported by the Silicon Labs ZigBee software stack, refer to the Table 2. Supported Serial Dataflash/EEPROM Remote Memory Parts, in Application Note AN772, Using Application Bootloader.
- Table 1: Silicon Labs Zigbee Serial Flash Vendor Parts List
- Manufacturer
- WinBond
- Part Number
- W25X20BVSNIG
- 2M (256K x 8)
- Description
- Software Driver
- spiflash-class1.c
- Macronix
- W25Q80BVSNIG
- MX25L2006EM1I-12G
- 8M (256K x 32)
- 2M (2M x 1, 1M x 2)
- MX25L8006EM1I-12G
- 8M (8M x 1, 4M x 2)
- Appendix B: Suggested 24MHz Crystal Providers for the EM35xx/0805 Ceramic Balun Front End 2-Layer Reference Design
- The tables below provide details for 24MHz crystal devices which can be used with EM35xx series ZigBee products for the manufacture of ZigBee radio devices.  Check with your preferred crystal vendor for the latest updates on their product offering or for additional information about crystals for the EM35xx ZigBee products in your target application.
- Table 2: Suggested 24MHz ZigBee Crystal Vendor Parts List for Crystal Packages Used in this design
- Package Size
- Frequency Tol
- Temperature Stability
- Aging
- Total Frequency Tol
- ESR
- Load Capacitance
- Tuning Capactor
- Abracon
- ABLS-24.000MHZ-D1X-T
- ABLS-24.000MHZ-D-R60-1-W-T
- ABLS-438-24.000MHZ-T
- HC/49US (AT49)
- +/- 10 ppm
- +/- 15ppm (-40 +85)
- +/- 20ppm (-40 +85)
- +/- 10 ppm/5 years
- +/-5 ppm/year
- +/-15 ppm/20 years
- 60 ohms
- 40 ohms
- 18pF
- 22pF
- ILSI
- AEL
- X24M000000S067
- HC49USM-24.000000M-2435
- HC49S SM
- HC49US
- +/- 10 ppm @25C
- +/- 25ppm (-40 +105)
- (-40 +85)
- +/- 3 ppm/year max
- 30 ohms
- 80 ohms
- 10pF
- Table 3: Suggested 24MHz ZigBee Crystal Vendor Parts List for High Temperature Rated Crystals Having Alternate Package/PCB Dimensions than is Used in this Design
- ABM3Y-101-24.000MHZ-T
- ABM8X-101-24.000MHZ
- 5.0 X 3.2 X 0.9mm
- 3.2 x 2.5 x 0.7mm
- +/- 25 ppm (-40 +105)
- +/- 25 ppm (-40 +125)
- +/- 5 ppm/10 years
- +/- 40 ppm (-40 +125)/10 years max
- 6.8pF
- EPSON
- X24M000000S037
- TSX-3225 24.0000MF20G-C
- ILCX07-24.000000M-2390
- 3.2 x 2.5 x 0.6mm
- 5.0 X 3.2 X 1.30mm
- +/- 20 ppm (-40 +105)
- (-40 +105)
- +/- 1 ppm/First year Max @ +25
- ILCX07-24.000000M-2392
- 3.2 x 2.5 x 0.9mm
- Table 4: Suggested 24MHz ZigBee Crystal Vendor Parts List for Commercial and Industrial Rated Crystals Having Alternate Package/PCB Dimensions than is Used in this Design
- ABM8-24.000MHZ-R60-D-1-W-T
- +/- 25 ppm (-40 +85)
- +/- 3 ppm/First year max @ +25
- ABM8-24.000MHZ-R60-D-1-G-T
- ABM8-177-24.000mHz
- +/- 15 ppm (-40 +85)
- +/- 15 ppm/20 years
- X24M000000S050
- X24M000000S058
- TSX-3225 24.0000MF18X-C 18pF
- +/- 18 ppm
- +/- 1 ppm/First year max @ +25
- +/- 15 ppm/20 years max
- 8.2pF
- 27pF
- ILCX13-24.000000M-2391
- ILCX07-24.000000M-2389
- KDS
- 1ZCA24000ZZ0C
- 1ZC224000ZZ0G
- 1C324000ZZ0D
- 2.5 x 2.0 x 0.75mm
- 3.2 x 2.5 x 0.75mm
- +/- 40 ppm (-40 +105)/10 years max
- Precision Devices, Inc.
- 1ZCB24000ZZ0B
- C324000XFAD13RX
- +/- 20 ppm (-40 +70)
- +/- 5 ppm/over life of the part
- 13pF
- 15pF
- Partron America Corp
- Suntsu
- TXC Technology
- CX5X24000FHVRG01
- SCM18D48-24.000MHZ
- 7B-24.000MEEQ-T
- 3.2 x 2.5 x 0.65mm
- +/- 10 ppm (-40 +85)
- +/- 2 ppm/ year @ +25
- +/- 2 ppm/1st Year max, then +/- 1ppm/year
- 7M-24.000MEEQ-T

## Sheet EM35xx_REF_DES_CER_AT1B_A1_Notes.SchDoc: EM35xx/0805 Ceramic Balun Reference Design
size C; Organization: MCU & Wireless Division Simplicity Support Group; Address1: 25 Thomson Place, 2nd Floor; Address2: Boston, MA 02210, USA; Address3: www.silabs.com; Address4: 617-951-0200; Revision: A1; SheetNumber: 5; SheetTotal: 5
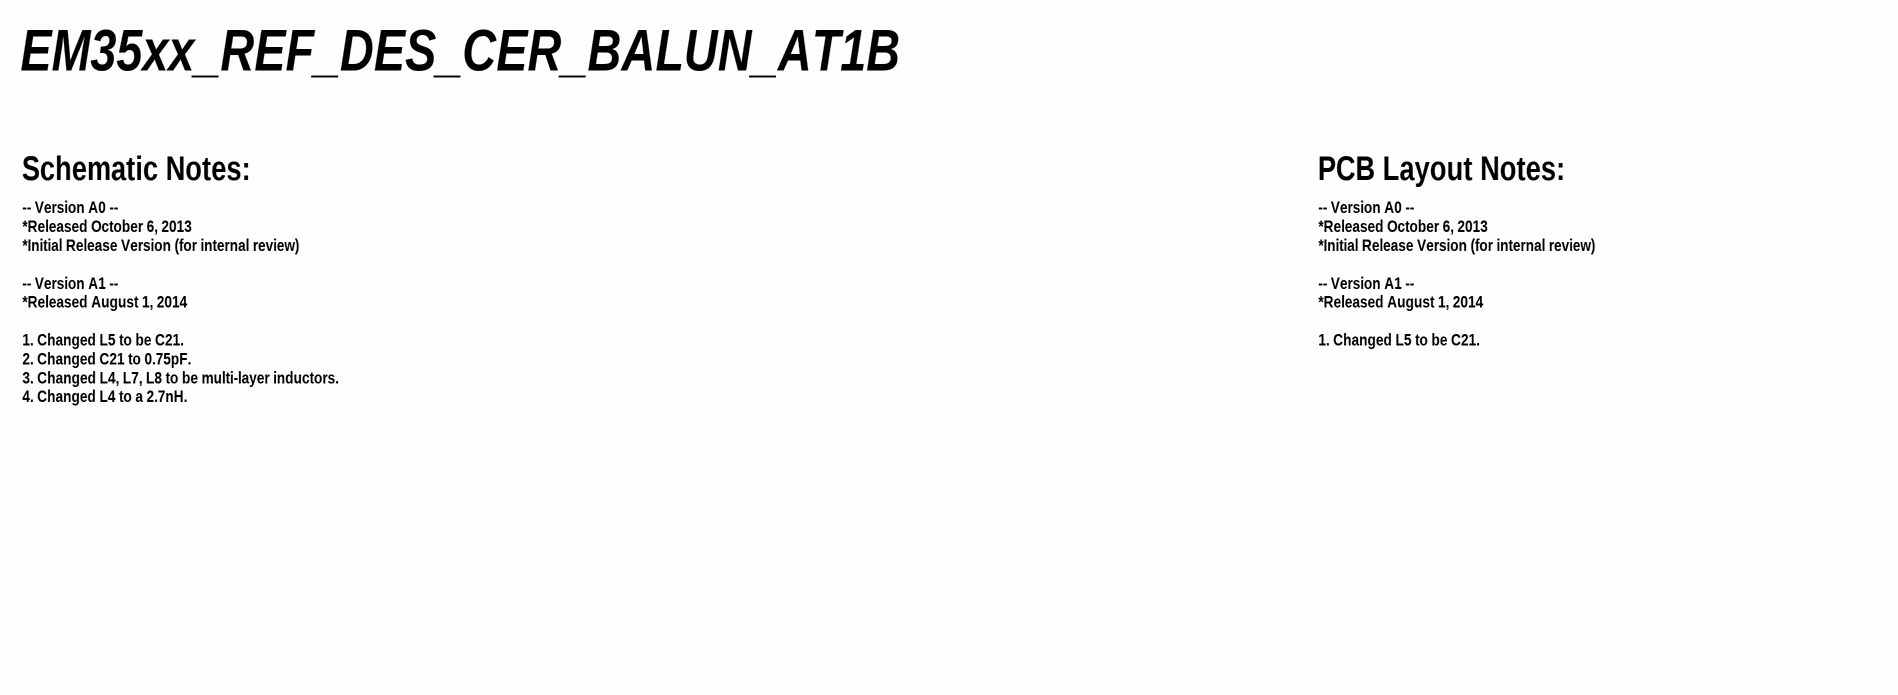
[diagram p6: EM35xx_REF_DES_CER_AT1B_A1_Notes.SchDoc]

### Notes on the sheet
- EM35xx_REF_DES_CER_BALUN_AT1B
- Schematic Notes:
- PCB Layout Notes:
- -- Version A0 --
  *Released October 6, 2013
  *Initial Release Version (for internal review)
  -- Version A1 --
  *Released August 1, 2014
  1.	Changed L5 to be C21.
  2.	Changed C21 to 0.75pF.
  3.	Changed L4, L7, L8 to be multi-layer inductors.
  4.	Changed L4 to a 2.7nH.
- -- Version A0 --
  *Released October 6, 2013
  *Initial Release Version (for internal review)
  -- Version A1 --
  *Released August 1, 2014
  1.	Changed L5 to be C21.

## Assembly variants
PCB0651-009_Proto_Assembly: not fitted L3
